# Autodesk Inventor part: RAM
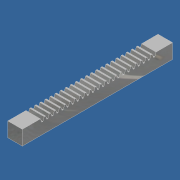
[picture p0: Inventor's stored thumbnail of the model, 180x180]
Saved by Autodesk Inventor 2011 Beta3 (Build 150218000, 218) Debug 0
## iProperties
Shininess: 64.0
Length Units: 11272
Angle Units: 11279
Time Units: 11290
Mass Units: 11286
Length Display Precision: 3
Angle Display Precision: 2
Compacted: True
Part Number: RAM
Document SubType Name: Modeling
Created: 2003-11
Designer: Autodesk, Inc.
Manufacturer: Standard
Standards Organization: Custom
Mass: 509.763 g
Surface Area: 178.528 cm^2
Volume: 65.0208 cm^3
Density: 7.84 g/cm^3
Material: Steel, High Strength Low Alloy
Density: 0.0
Volumn: 0.0
Area: 0.0
PropertySet Name: Model Information
Control State: 0
Master: False
Checked Out: False
Author: Autodesk, Inc.
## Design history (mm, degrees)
sketch "Sketch1"
  geometry: L1 (0, 0)-(19.05, 0); L2 (19.05, 0)-(19.05, 19.05); L3 (19.05, 19.05)-(0, 19.05); L4 (0, 19.05)-(0, 0)
  constraints: 8 end point, 2 parallel, 1 horizontal, 1 perpendicular
  dimensions: "d0" = 19.05 distance of L1.start L1.end; "d1" = 19.05 distance of L1.end L2.end
extrude "Extrusion1" new body sketch "Sketch1" distance "d2" = 196.85; taper "d3" = 0 deg
sketch "Sketch2"
  geometry: L1 (0, 0)-(0, 19.05) reference; L2 (0, 19.05)-(-196.85, 19.05) reference; L3 (-196.85, 19.05)-(-196.85, 0) reference; L4 (0, 0)-(-196.85, 0) reference; L5 (-168.185, 19.05)-(-166.4, 19.05); L6 (-166.4, 19.05)-(-164.739, 14.486); L7 (-168.185, 19.05)-(-169.846, 14.486); L8 (-167.293, 19.05)-(-167.293, 27.541); L9 (-130.145, 19.823)-(-130.145, 4.561); L10 (-173.431, 16.934)-(-94.815, 16.934); L11 (-163.197, 14.486)-(-161.535, 19.05); L12 (-161.535, 19.05)-(-159.751, 19.05); L13 (-159.751, 19.05)-(-158.089, 14.486); L14 (-164.739, 14.486)-(-163.197, 14.486); L15 (-158.089, 14.486)-(-24.993, 14.486); L16 (-160.643, 19.05)-(-160.643, 25.268); L17 (-169.846, 14.486)-(-171.389, 14.486); L18 (-171.389, 14.486)-(-173.05, 19.05); L19 (-156.542, 14.486)-(-154.881, 19.05); L20 (-154.881, 19.05)-(-153.096, 19.05); L21 (-153.096, 19.05)-(-151.435, 14.486); L22 (-149.887, 14.486)-(-148.226, 19.05); L23 (-148.226, 19.05)-(-146.441, 19.05); L24 (-146.441, 19.05)-(-144.78, 14.486); L25 (-143.232, 14.486)-(-141.571, 19.05); L26 (-141.571, 19.05)-(-139.786, 19.05); L27 (-139.786, 19.05)-(-138.125, 14.486); L28 (-136.578, 14.486)-(-134.916, 19.05); L29 (-134.916, 19.05)-(-133.132, 19.05); L30 (-133.132, 19.05)-(-131.47, 14.486); L31 (-129.923, 14.486)-(-128.261, 19.05); L32 (-128.261, 19.05)-(-126.477, 19.05); L33 (-126.477, 19.05)-(-124.815, 14.486); L34 (-123.268, 14.486)-(-121.607, 19.05); L35 (-121.607, 19.05)-(-119.822, 19.05); L36 (-119.822, 19.05)-(-118.161, 14.486); L37 (-116.613, 14.486)-(-114.952, 19.05); L38 (-114.952, 19.05)-(-113.167, 19.05); L39 (-113.167, 19.05)-(-111.506, 14.486); L40 (-109.958, 14.486)-(-108.297, 19.05); L41 (-108.297, 19.05)-(-106.512, 19.05); L42 (-106.512, 19.05)-(-104.851, 14.486); L43 (-103.304, 14.486)-(-101.642, 19.05); L44 (-101.642, 19.05)-(-99.858, 19.05); L45 (-99.858, 19.05)-(-98.196, 14.486); L46 (-96.649, 14.486)-(-94.987, 19.05); L47 (-94.987, 19.05)-(-93.203, 19.05); L48 (-93.203, 19.05)-(-91.541, 14.486); L49 (-89.994, 14.486)-(-88.333, 19.05); L50 (-88.333, 19.05)-(-86.548, 19.05); L51 (-86.548, 19.05)-(-84.887, 14.486); L52 (-83.339, 14.486)-(-81.678, 19.05); L53 (-81.678, 19.05)-(-79.893, 19.05); L54 (-79.893, 19.05)-(-78.232, 14.486); L55 (-76.684, 14.486)-(-75.023, 19.05); L56 (-75.023, 19.05)-(-73.238, 19.05); L57 (-73.238, 19.05)-(-71.577, 14.486); L58 (-70.03, 14.486)-(-68.368, 19.05); L59 (-68.368, 19.05)-(-66.584, 19.05); L60 (-66.584, 19.05)-(-64.922, 14.486); L61 (-63.375, 14.486)-(-61.713, 19.05); L62 (-61.713, 19.05)-(-59.929, 19.05); L63 (-59.929, 19.05)-(-58.267, 14.486); L64 (-56.72, 14.486)-(-55.059, 19.05)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; 65 further points
  constraints: 201 end point, 53 point on line, 27 collinear, 10 parallel, 3 perpendicular, 2 midpoint, 1 coincident, 1 horizontal, 200 other
  dimensions: "d5" = 2.11582 distance between parallel lines of L10 L5; "d6" = 20 deg angle of L8 L7; "d7" = 20 deg angle of L6 L8; "d11" = 6.64972 distance between parallel lines of L16 L8; "d12" = 3.32486 distance of point (-165.63, 16.934) point (-168.955, 16.934); "d13" = 3.32486 distance of point (-158.981, 16.934) point (-162.306, 16.934) (= d12); "d14" = 3.32486 distance of point (-168.955, 16.934) point (-172.28, 16.934) (= d12); "d15" = 23.7998 distance from line of L3 L18.end; "d16" = 2.44856 distance between parallel lines of L17 L10; "d19" = 6.6548 distance of L11.start L19.start
extrude "Extrusion2" sketch "Sketch2" stored distance "d24" = 25.4; taper "d25" = 0 deg
sketch "Sketch5"
  geometry: L1 (126.82, 14.486)-(128.482, 19.05) reference; L2 (125.273, 14.486)-(126.82, 14.486) reference; L3 (123.612, 19.05)-(125.273, 14.486) reference; L4 (123.612, 19.05)-(121.827, 19.05) reference; L5 (120.166, 14.486)-(121.827, 19.05) reference; L6 (118.618, 14.486)-(120.166, 14.486) reference; L7 (116.957, 19.05)-(118.618, 14.486) reference; L8 (116.957, 19.05)-(115.172, 19.05) reference; L9 (113.511, 14.486)-(115.172, 19.05) reference; L10 (111.963, 14.486)-(113.511, 14.486) reference; L11 (110.302, 19.05)-(111.963, 14.486) reference; L12 (110.302, 19.05)-(108.517, 19.05) reference; L13 (106.856, 14.486)-(108.517, 19.05) reference; L14 (105.309, 14.486)-(106.856, 14.486) reference; L15 (103.647, 19.05)-(105.309, 14.486) reference; L16 (103.647, 19.05)-(101.863, 19.05) reference; L17 (100.201, 14.486)-(101.863, 19.05) reference; L18 (98.654, 14.486)-(100.201, 14.486) reference; L19 (96.992, 19.05)-(98.654, 14.486) reference; L20 (96.992, 19.05)-(95.208, 19.05) reference; L21 (93.546, 14.486)-(95.208, 19.05) reference; L22 (91.999, 14.486)-(93.546, 14.486) reference; L23 (90.338, 19.05)-(91.999, 14.486) reference; L24 (90.338, 19.05)-(88.553, 19.05) reference; L25 (86.892, 14.486)-(88.553, 19.05) reference; L26 (85.344, 14.486)-(86.892, 14.486) reference; L27 (83.683, 19.05)-(85.344, 14.486) reference; L28 (83.683, 19.05)-(81.898, 19.05) reference; L29 (80.237, 14.486)-(81.898, 19.05) reference; L30 (78.689, 14.486)-(80.237, 14.486) reference; L31 (77.028, 19.05)-(78.689, 14.486) reference; L32 (77.028, 19.05)-(75.243, 19.05) reference; L33 (73.582, 14.486)-(75.243, 19.05) reference; L34 (72.035, 14.486)-(73.582, 14.486) reference; L35 (70.373, 19.05)-(72.035, 14.486) reference; L36 (70.373, 19.05)-(68.589, 19.05) reference; L37 (66.927, 14.486)-(68.589, 19.05) reference; L38 (65.38, 14.486)-(66.927, 14.486) reference; L39 (63.718, 19.05)-(65.38, 14.486) reference; L40 (63.718, 19.05)-(61.934, 19.05) reference; L41 (60.272, 14.486)-(61.934, 19.05) reference; L42 (58.725, 14.486)-(60.272, 14.486) reference; L43 (57.064, 19.05)-(58.725, 14.486) reference; L44 (57.064, 19.05)-(55.279, 19.05) reference; L45 (53.618, 14.486)-(55.279, 19.05) reference; L46 (52.07, 14.486)-(53.618, 14.486) reference; L47 (50.409, 19.05)-(52.07, 14.486) reference; L48 (50.409, 19.05)-(48.624, 19.05) reference; L49 (46.963, 14.486)-(48.624, 19.05) reference; L50 (45.415, 14.486)-(46.963, 14.486) reference; L51 (43.754, 19.05)-(45.415, 14.486) reference; L52 (43.754, 19.05)-(41.969, 19.05) reference; L53 (40.308, 14.486)-(41.969, 19.05) reference; L54 (38.761, 14.486)-(40.308, 14.486) reference; L55 (37.099, 19.05)-(38.761, 14.486) reference; L56 (37.099, 19.05)-(35.315, 19.05) reference; L57 (33.653, 14.486)-(35.315, 19.05) reference; L58 (32.111, 14.486)-(33.653, 14.486) reference; L59 (30.45, 19.05)-(32.111, 14.486) reference; L60 (30.45, 19.05)-(28.665, 19.05) reference; L61 (27.004, 14.486)-(28.665, 19.05) reference; L62 (25.461, 14.486)-(27.004, 14.486) reference; L63 (23.8, 19.05)-(25.461, 14.486) reference; L64 (23.8, 19.05)-(0, 19.05) reference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
  constraints: 10 end point, 3 parallel, 2 collinear, 2 point on line
  dimensions: "d26" = 1.5494 distance of L94.end L95.end; "d27" = 1.905 distance of L68.end L93.end
extrude "Extrusion3" cut sketch "Sketch5" distance "d28" = 25.4; taper "d29" = 0 deg
body "Solid1"
node "Projected Loop1"
node "Projected Loop4"
other parameters: "d22" = 25.4
